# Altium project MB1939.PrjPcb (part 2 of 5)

## Sheet MEMs_microphone.SchDoc: MEMs_microphone
size A4; Date: Not used; ApprovedBy: Not used; CheckedBy: Not used; Author: Not used; CompanyName: STMicroelectronics; DrawnBy: Not used; Engineer: Not used; Organization: Not used; Address1: Not used; Address2: Not used; Address3: Not used; Address4: Not used; DocumentNumber: Not used; Revision: Not used; SheetNumber: 16; SheetTotal: 21
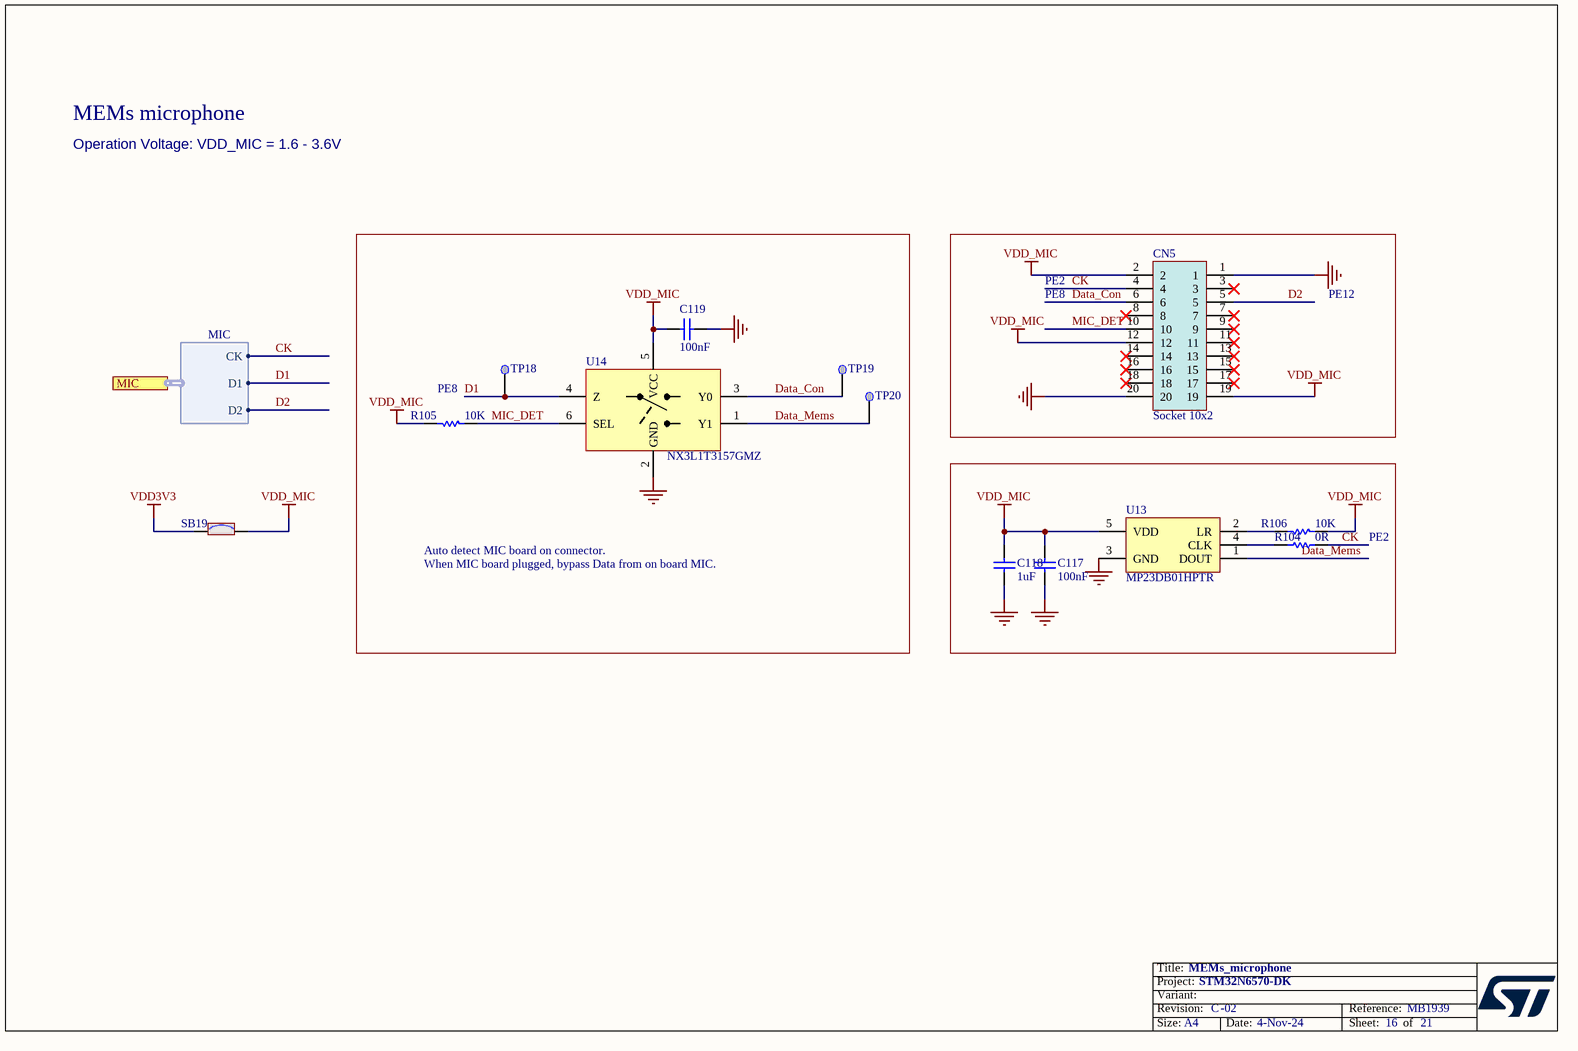
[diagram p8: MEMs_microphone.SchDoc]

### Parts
C117  value 100nF  [C0402]  (hidden comment: Capacitor)
C118  value 1uF  [C0402]  (hidden comment: Capacitor)
C119  value 100nF  [C0402]  (hidden comment: Capacitor)
CN5  Socket 10x2  [CON_FCI_20021311-XXX20XXLF]
R104  value 0R  [R0402]  (hidden comment: Resistor)
R105  value 10K  [R0402]  (hidden comment: Resistor)
R106  value 10K  [R0402]  (hidden comment: Resistor)
SB19  SB_ON  [SOLDER-BRIDGE_R0402-0R]  (value not drawn)
TP18  Test Point  [TP_SMD_1MM]  (value not drawn)  (no BOM)
TP19  Test Point  [TP_SMD_1MM]  (value not drawn)  (no BOM)
TP20  Test Point  [TP_SMD_1MM]  (value not drawn)  (no BOM)
U13  value MP23DB01HPTR  [MIC_STM_MP23DB01MMTR]  (hidden comment: MP23DB01MMTR)
U14  value NX3L1T3157GMZ  [ICC_SOT886_XSON6]  (hidden comment: NX3L1T3157GM)

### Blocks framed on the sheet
PE2: C117 C118 R104 R106 U13

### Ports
MIC (harness MIC)

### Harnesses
MIC: CK, D1, D2

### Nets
GND: C117.1 C118.1 C119.1 CN5.1 CN5.20 U13.3(GND) U14.2(GND)
VDD3V3: SB19.1
VDD_MIC: C117.2 C118.2 C119.2 CN5.2 CN5.12 CN5.19 R105.2 R106.1 SB19.2 U13.5(VDD) U14.5(VCC)
CK: CN5.4 R104.2 ; port MIC.CK
D1: TP18.1 U14.4(Z) ; port MIC.D1
D2: CN5.5 ; port MIC.D2
Data_Con: CN5.6 TP19.1 U14.3(Y0)
Data_Mems: TP20.1 U13.1(DOUT) U14.1(Y1)
MIC_DET: CN5.10 R105.1 U14.6(SEL)
NetR104_1: R104.1 U13.4(CLK)
NetR106_2: R106.2 U13.2(LR)

Not connected (* = marked no-connect by the designer): CN5 3* 7* 8* 9* 11* 13* 14* 15* 16* 17* 18*

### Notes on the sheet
- MEMs microphone
- Operation Voltage: VDD_MIC = 1.6 - 3.6V
- PE2
- PE8
- PE12
- (near R105) PE8
- Auto detect MIC board on connector.
- When MIC board plugged, bypass Data from on board MIC.
- Title:
- Project:
- Size:
- Revision:
- Variant:
- A4
- -
- Date:
- Reference:
- Sheet:
- of

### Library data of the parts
C117 C119 = MCD-00006: Capacitor, MLCC, 100nF, 16V, X7R, +/-10%, 0402, T=0.5mm; Manufacturer_Part_Number: CC0402KRX7R7BB104; Manufacturer: YAGEO; Part_Preference: Recommended; Partial_Alternate_Internal_Part_Number: MCD-03299; Order_Code_RS: 9402047; Component_Country_Of_Origin: China; ShowFields: YES; ID: 2474
C118 = MCD-00095: Capacitor, MLCC, 1uF, 25V, X5R, +/-10%, 0402, T=0.5mm; Part_Preference: Recommended; Manufacturer: MURATA; Manufacturer_Part_Number: GRM155R61E105KA12; Partial_Alternate_Internal_Part_Number: MCD-04188; Order_Code_RS: 2218855; Component_Country_Of_Origin: Japan°°; ShowFields: YES; ID: 2772
CN5 = MCD-00147: Socket, 10x2, 1.27mm, VR, TH, T=4.30mm/2.40mm; Part_Type: Connector; Part_Preference: Recommended; Manufacturer: AMPHENOL CS; Manufacturer_Part_Number: 20021311-00020T4LF; Partial_Alternate_Internal_Part_Number: MCD-03007; Order_Code_RS: 170-8859; Component_Country_Of_Origin: China; ShowFields: YES; ID: 2719
R104 = MCD-00052: Resistor, 0R, 0402, +/-5%, 1/16W; Manufacturer_Part_Number: RC0402JR-070RL; Manufacturer: YAGEO; Part_Preference: Recommended; Order_Code_RS: 9232516RL; Component_Country_Of_Origin: China; ShowFields: YES; ID: 2540
R105 R106 = MCD-00053: Resistor, 10K, 0402, +/-1%, 1/16W; Manufacturer_Part_Number: RC0402FR-0710KL; Manufacturer: YAGEO; BMS_Part_Number: 9131590; Part_Preference: Recommended; Order_Code_RS: 9239359; Component_Country_Of_Origin: China; ShowFields: YES; ID: 2539
SB19 = MCD-01618: Resistor, 0R, SB0402, 5%, 0.063W; Manufacturer_Part_Number: RC0402JR-070RL; Manufacturer: YAGEO; Part_Preference: Recommended; Order_Code_RS: 618-5804; Component_Country_Of_Origin: China; ShowFields: YES; ID: 3718
TP18-TP20 = MCD-00074: Test Point, SMD, 1mm; Part_Type: Misc; Part_Preference: Recommended; ShowFields: YES; ID: 2518; Component_Country_Of_Origin: Unknown
U13 = MCD-02122: MEMS, Audio sensor Multi performance mode digital microphone; Part_Type: IC; Manufacturer: STMICROELECTRONICS; Part_Preference: Recommended; Manufacturer_HQ_COO: EU; Component_Country_Of_Origin: China; ShowFields: YES; ID: 4222
U14 = MCD-02386: Analog Switch, Low-ohmic single-pole double-throw analog switch; Part_Type: IC; Part_Preference: Recommended; Manufacturer: NXP; Partial_Alternate_Internal_Part_Number: MCD-03199; Component_Country_Of_Origin: Thailand; ShowFields: YES; ID: 4492

## Sheet OctoSPI_Flash.SchDoc: OctoSPI_Flash
size A4; Date: Not used; ApprovedBy: Not used; CheckedBy: Not used; Author: Not used; CompanyName: STMicroelectronics; DrawnBy: Not used; Engineer: Not used; Organization: Not used; Address1: Not used; Address2: Not used; Address3: Not used; Address4: Not used; DocumentNumber: Not used; Revision: Not used; SheetNumber: 7; SheetTotal: 21
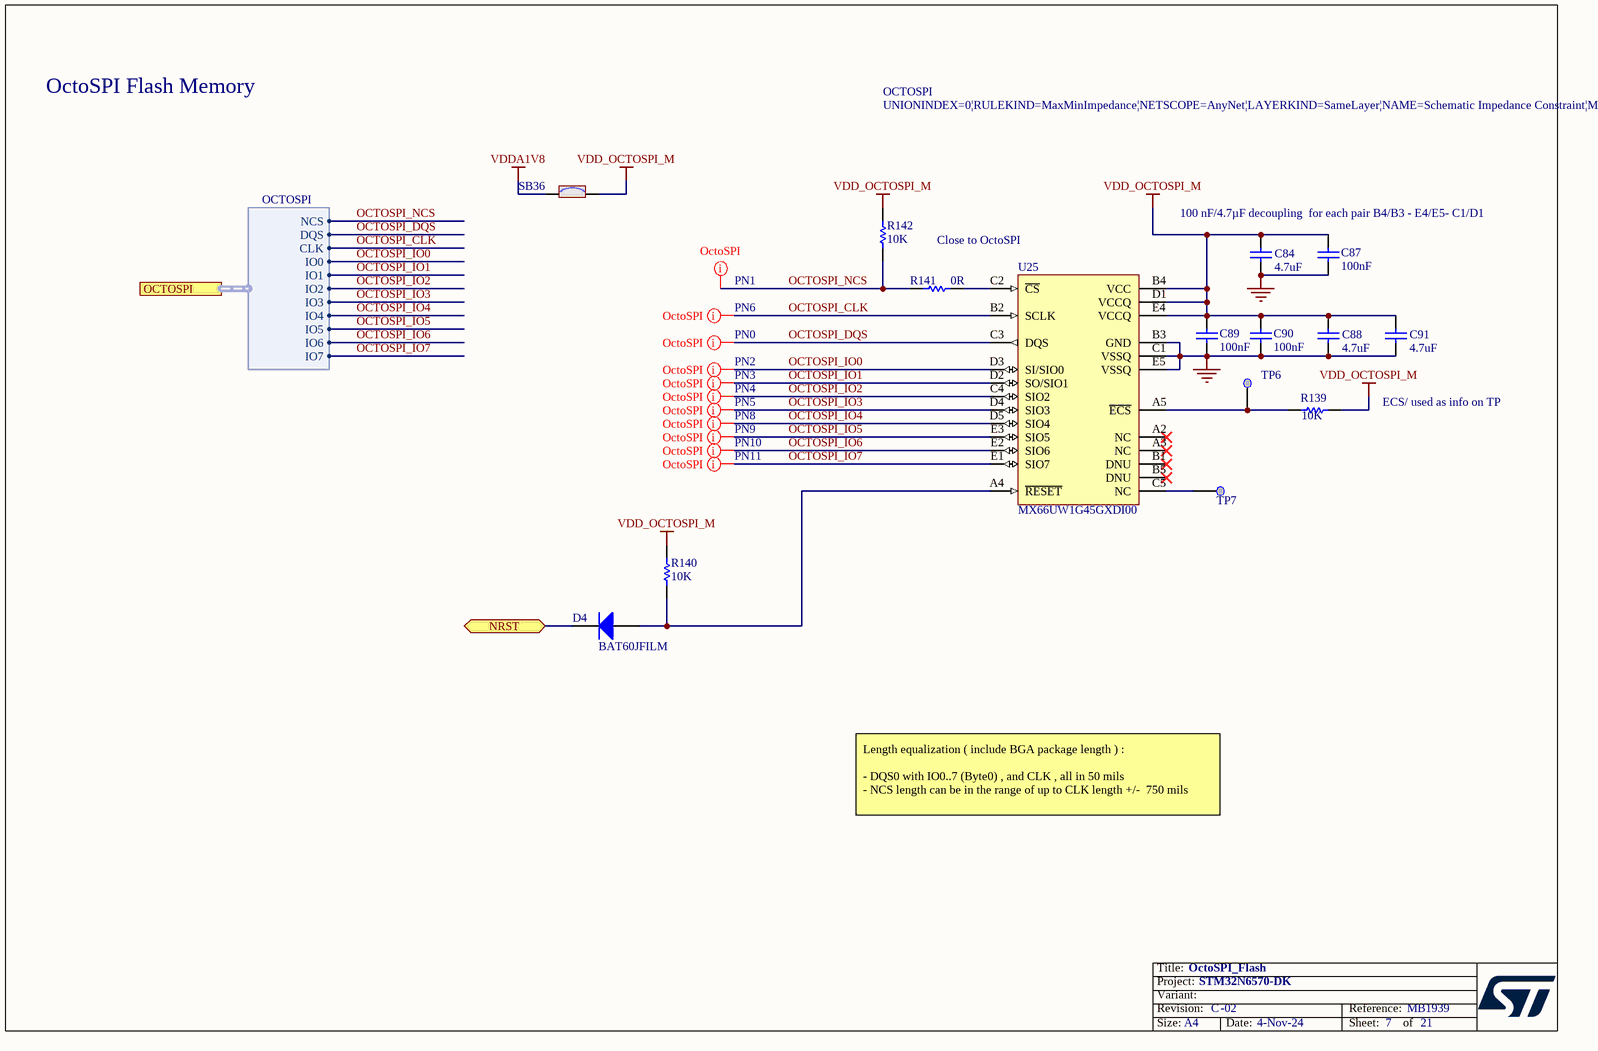
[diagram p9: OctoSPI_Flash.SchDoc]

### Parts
C84  value 4.7uF  [C0603]  (hidden comment: Capacitor)
C87  value 100nF  [C0402]  (hidden comment: Capacitor)
C88  value 4.7uF  [C0603]  (hidden comment: Capacitor)
C89  value 100nF  [C0402]  (hidden comment: Capacitor)
C90  value 100nF  [C0402]  (hidden comment: Capacitor)
C91  value 4.7uF  [C0603]  (hidden comment: Capacitor)
D4  BAT60JFILM  [DIO_SOD323]
R139  value 10K  [R0402]  (hidden comment: Resistor)
R140  value 10K  [R0402]  (hidden comment: Resistor)
R141  value 0R  [R0402]  (hidden comment: Resistor)
R142  value 10K  [R0402]  (hidden comment: Resistor)
SB36  SB_ON  [SOLDER-BRIDGE_R0402-0R]  (value not drawn)
TP6  Test Point  [TP_SMD_1MM]  (value not drawn)  (no BOM)
TP7  Test Point  [TP_SMD_1MM]  (value not drawn)  (no BOM)
U25  MX66UW1G45GXDI00  [ICC_BGA24_5X5-BALL-ARRAY_6X8_P1]

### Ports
NRST (bidir), OCTOSPI (harness OCTOSPI)

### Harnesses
OCTOSPI: IO1, IO0, CLK, NCS, IO2, IO3, IO5, IO4, IO6, IO7, DQS

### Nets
GND: C84.1 C87.1 C88.1 C89.1 C90.1 C91.1 U25.B3(GND) U25.C1(VSSQ) U25.E5(VSSQ)
VDD_OCTOSPI_M: C84.2 C87.2 C88.2 C89.2 C90.2 C91.2 R139.2 R140.2 R142.2 SB36.2 U25.B4(VCC) U25.D1(VCCQ) U25.E4(VCCQ)
VDDA1V8: SB36.1
NRST: D4.2(K) ; port NRST
OCTOSPI_CLK: U25.B2(SCLK) ; port OCTOSPI.CLK
OCTOSPI_DQS: U25.C3(DQS) ; port OCTOSPI.DQS
OCTOSPI_IO0: U25.D3(SI/SIO0) ; port OCTOSPI.IO0
OCTOSPI_IO1: U25.D2(SO/SIO1) ; port OCTOSPI.IO1
OCTOSPI_IO2: U25.C4(SIO2) ; port OCTOSPI.IO2
OCTOSPI_IO3: U25.D4(SIO3) ; port OCTOSPI.IO3
OCTOSPI_IO4: U25.D5(SIO4) ; port OCTOSPI.IO4
OCTOSPI_IO5: U25.E3(SIO5) ; port OCTOSPI.IO5
OCTOSPI_IO6: U25.E2(SIO6) ; port OCTOSPI.IO6
OCTOSPI_IO7: U25.E1(SIO7) ; port OCTOSPI.IO7
OCTOSPI_NCS: R141.1 R142.1 ; port OCTOSPI.NCS
NetD4_1: D4.1(A) R140.1 U25.A4(~{RESET})
NetR139_1: R139.1 TP6.1 U25.A5(~{ECS})
NetR141_2: R141.2 U25.C2(~{CS})
NetTP7_1: TP7.1 U25.C5(NC)

Not connected (* = marked no-connect by the designer): U25 A2(NC)* A3(NC)* B1(DNU)* B5(DNU)*

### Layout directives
rule Matched Net Lengths [Tolerance = 1000mil]; net class OCTOSPI; rule Impedance Constraint [Min = 45.00    Max = 55.00    ]; rule Routing Layers [TopLayer - Enabled BottomLayer - Disabled]: OCTOSPI_NCS
rule Matched Net Lengths [Tolerance = 10mil]; net class OCTOSPI; rule Impedance Constraint [Min = 45.00    Max = 55.00    ]; rule Routing Layers [TopLayer - Enabled BottomLayer - Disabled]: OCTOSPI_CLK
rule Matched Net Lengths [Tolerance = 20mil]; net class OCTOSPI; rule Impedance Constraint [Min = 45.00    Max = 55.00    ]; rule Routing Layers [TopLayer - Enabled BottomLayer - Disabled]: OCTOSPI_DQS, OCTOSPI_IO0, OCTOSPI_IO1, OCTOSPI_IO2, OCTOSPI_IO3, OCTOSPI_IO4, OCTOSPI_IO5, OCTOSPI_IO6, OCTOSPI_IO7

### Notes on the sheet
- OctoSPI Flash Memory
- Close to OctoSPI
- 100 nF/4.7µF decoupling  for each pair B4/B3 - E4/E5- C1/D1
- PN1
- PN6
- PN3
- PN2
- PN0
- PN10
- PN9
- PN5
- PN8
- PN4
- ECS/ used as info on TP
- PN11
- Length equalization ( include BGA package length ) :
  - DQS0 with IO0..7 (Byte0) , and CLK , all in 50 mils
  - NCS length can be in the range of up to CLK length +/-  750 mils
- Title:
- Project:
- Size:
- Revision:
- Variant:
- A4
- -
- Date:
- Reference:
- Sheet:
- of

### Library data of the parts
C84 C88 C91 = MCD-00009: Capacitor, MLCC, 4.7uF, 16V, X5R, +/-10%, 0603, T=0.8mm; Manufacturer_Part_Number: CC0603KRX5R7BB475; Manufacturer: YAGEO; Part_Preference: Recommended; Partial_Alternate_Internal_Part_Number: MCD-03565; Component_Country_Of_Origin: China; ShowFields: YES; ID: 2471; Alternate_EMS: A
C87 C89 C90 = MCD-00006: as C117 on sheet MEMs_microphone
D4 = MCD-00034: Diode, Schottky, 0V53, 1A, 10V, SOD323; Manufacturer: STMICROELECTRONICS; BMS_Part_Number: 9151097; Part_Preference: Recommended; Manufacturer_HQ_COO: EU; Component_Country_Of_Origin: China; ShowFields: YES; ID: 2483; Order_Code_RS: 714-6879
R139 R140 R142 = MCD-00053: as R105 on sheet MEMs_microphone
R141 = MCD-00052: as R104 on sheet MEMs_microphone
SB36 = MCD-01618: as SB19 on sheet MEMs_microphone
TP6 TP7 = MCD-00074: as TP18 on sheet MEMs_microphone
U25 = MCD-02601: Memory, Serial NOR Flash, 1V8, 1Gbit, 200MHz, BGA-24; Part_Type: IC; Part_Preference: Recommended; Manufacturer: MACRONIX; Manufacturer_HQ_COO: Unknown; ShowFields: YES; ID: 4707; Component_Country_Of_Origin: Taiwan

## Sheet SDcard.SchDoc: SD Card
size A4; Date: Not used; ApprovedBy: Not used; CheckedBy: Not used; Author: Not used; CompanyName: STMicroelectronics; DrawnBy: Not used; Engineer: Not used; Organization: Not used; Address1: Not used; Address2: Not used; Address3: Not used; Address4: Not used; DocumentNumber: Not used; Revision: Not used; SheetNumber: 14; SheetTotal: 21
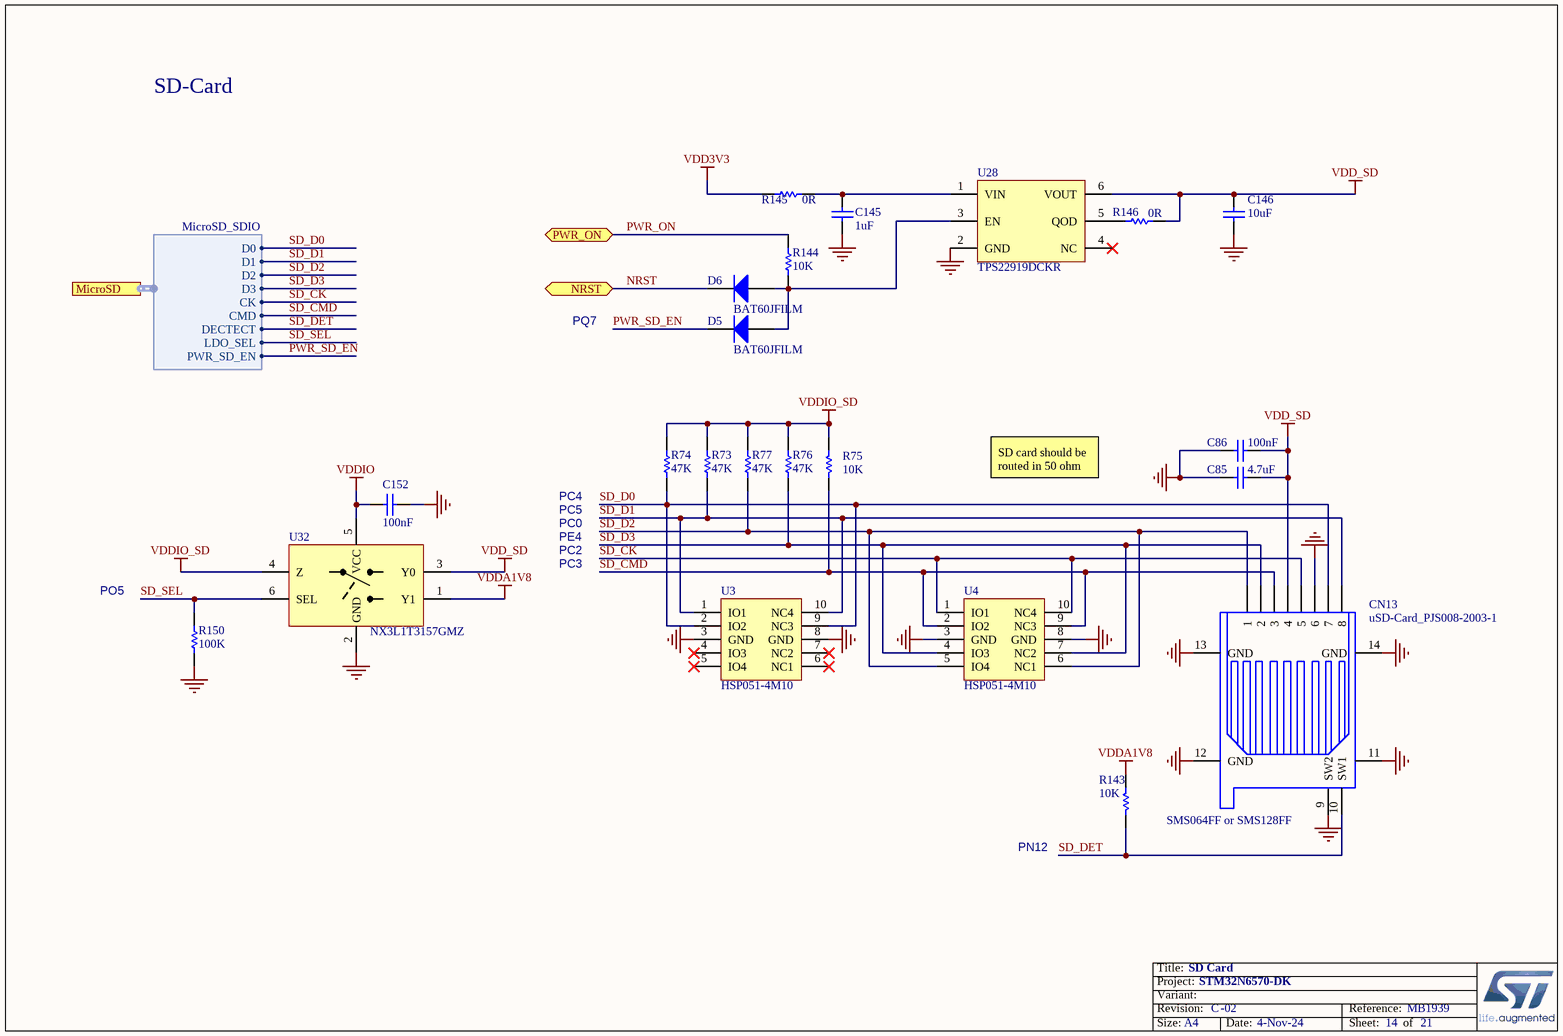
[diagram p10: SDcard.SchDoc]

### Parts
C85  value 4.7uF  [C0603]  (hidden comment: Capacitor)
C86  value 100nF  [C0402]  (hidden comment: Capacitor)
C145  value 1uF  [C0402]  (hidden comment: Capacitor)
C146  value 10uF  [C0603]  (hidden comment: Capacitor)
C152  value 100nF  [C0402]  (hidden comment: Capacitor)
CN13  value uSD-Card_PJS008-2003-1  [CON_MICROSD_YAMAICHI_PJS008-2003-1]  (hidden comment: microSD-PJS008-2003)
D5  BAT60JFILM  [DIO_SOD323]
D6  BAT60JFILM  [DIO_SOD323]
R73  value 47K  [R0402]  (hidden comment: Resistor)
R74  value 47K  [R0402]  (hidden comment: Resistor)
R75  value 10K  [R0402]  (hidden comment: Resistor)
R76  value 47K  [R0402]  (hidden comment: Resistor)
R77  value 47K  [R0402]  (hidden comment: Resistor)
R143  value 10K  [R0402]  (hidden comment: Resistor)
R144  value 10K  [R0402]  (hidden comment: Resistor)
R145  value 0R  [R0603]  (hidden comment: Resistor)
R146  value 0R  [R0402]  (hidden comment: Resistor)
R150  value 100K  [R0402]  (hidden comment: Resistor)
U3  HSP051-4M10  [ESD_UQFN-10L_2P5X1_P050]
U4  HSP051-4M10  [ESD_UQFN-10L_2P5X1_P050]
U28  value TPS22919DCKR  [ICC_SC70-6_DCK_R-PDSO-G6_2X1P25_P065]  (hidden comment: TPS22919)
U32  value NX3L1T3157GMZ  [ICC_SOT886_XSON6]  (hidden comment: NX3L1T3157GM)

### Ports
MicroSD (harness MicroSD_SDIO), NRST (bidir), PWR_ON (bidir)

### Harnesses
MicroSD_SDIO: D0, D1, D2, D3, CK, CMD, DECTECT, LDO_SEL, PWR_SD_EN

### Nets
GND: C85.2 C86.1 C145.1 C146.1 C152.1 CN13.6 CN13.9(SW2) CN13.11(GND) CN13.12(GND) CN13.13(GND) CN13.14(GND) R150.1 U3.3(GND) U3.8(GND) U4.3(GND) U4.8(GND) U28.2(GND) U32.2(GND)
VDD3V3: R145.1
VDD_SD: C85.1 C86.2 C146.2 CN13.4 R146.2 U28.6(VOUT) U32.3(Y0)
VDDA1V8: R143.2 U32.1(Y1)
VDDIO: C152.2 U32.5(VCC)
VDDIO_SD: R73.2 R74.2 R75.2 R76.2 R77.2 U32.4(Z)
NRST: D6.2(K) ; port NRST
PWR_ON: R144.1 ; port PWR_ON
PWR_SD_EN: D5.2(K) ; port MicroSD.PWR_SD_EN  [project net PQ7]
SD_CK: CN13.5 U4.1(IO1) U4.10(NC4) ; port MicroSD.CK  [project net PC2]
SD_CMD: CN13.3 R75.1 U4.2(IO2) U4.9(NC3) ; port MicroSD.CMD  [project net PC3]
SD_D0: CN13.7 R74.1 U3.2(IO2) U3.9(NC3) ; port MicroSD.D0  [project net PC4]
SD_D1: CN13.8 R73.1 U3.1(IO1) U3.10(NC4) ; port MicroSD.D1  [project net PC5]
SD_D2: CN13.1 R77.1 U4.5(IO4) U4.6(NC1) ; port MicroSD.D2  [project net PC0]
SD_D3: CN13.2 R76.1 U4.4(IO3) U4.7(NC2) ; port MicroSD.D3  [project net PE4]
SD_DET: CN13.10(SW1) R143.1 ; port MicroSD.DECTECT  [project net PN12]
SD_SEL: R150.2 U32.6(SEL) ; port MicroSD.LDO_SEL  [project net PO5]
NetC145_2: C145.2 R145.2 U28.1(VIN)
NetD5_1: D5.1(A) D6.1(A) R144.2 U28.3(EN)
NetR146_1: R146.1 U28.5(QOD)

Not connected (* = marked no-connect by the designer): U3 4(IO3)* 5(IO4)* 6(NC1)* 7(NC2)*; U28 4(NC)*

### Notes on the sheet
- SD-Card
- PQ7
- PC4
- PC5
- SD card should be routed in 50 ohm
- PC0
- PE4
- PC3
- PC2
- PO5
- PN12
- SMS064FF or SMS128FF

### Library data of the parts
C85 = MCD-00009: as C84 on sheet OctoSPI_Flash
C86 C152 = MCD-00006: as C117 on sheet MEMs_microphone
C145 = MCD-00095: Capacitor, MLCC, 1uF, 25V, X5R, +/-10%, 0402, T=0.5mm; Manufacturer_Part_Number: GRM155R61E105KA12; Manufacturer: MURATA; Part_Preference: Recommended; Partial_Alternate_Internal_Part_Number: MCD-04188; Order_Code_RS: 2218855; Component_Country_Of_Origin: Japan°°; ShowFields: YES; ID: 2772
C146 = MCD-00099: Capacitor, MLCC, 10uF, 10V, X5R, +/-10%, 0603, T=0.8mm; Manufacturer_Part_Number: GRM188R61A106KE69D; Manufacturer: MURATA; Part_Preference: Recommended; Partial_Alternate_Internal_Part_Number: MCD-03152; Order_Code_RS: 2494233; Component_Country_Of_Origin: Japan°°; ShowFields: YES; ID: 2770
CN13 = MCD-00023: Connector_uSD Card, Reversed-Type, Mnt Push-Push; Manufacturer_Part_Number: PJS008-2003-1; Manufacturer: YAMAICHI; Part_Preference: Recommended; Component_Country_Of_Origin: Unknown; ShowFields: YES; ID: 2492
D5 D6 = MCD-00034: as D4 on sheet OctoSPI_Flash
R73 R74 R76 R77 = MCD-00063: Resistor, 47K, 0402, +/-1%, 1/16W; Manufacturer_Part_Number: RC0402FR-0747KL; Manufacturer: YAGEO; Part_Preference: Recommended; Order_Code_RS: 9239430; Component_Country_Of_Origin: China; ShowFields: YES; ID: 2528
R75 R143 R144 = MCD-00053: as R105 on sheet MEMs_microphone
R145 = MCD-00056: Resistor, 0R, 0603, +/-5%, 1/10W; Manufacturer_Part_Number: RC0603JR-070RL; Manufacturer: YAGEO; Part_Preference: Recommended; Order_Code_RS: 9233130RL; Component_Country_Of_Origin: China; ShowFields: YES; ID: 2536
R146 = MCD-00052: as R104 on sheet MEMs_microphone
R150 = MCD-00059: Resistor, 100K, 0402, +/-1%, 1/16W; Manufacturer_Part_Number: RC0402FR-07100KL; Manufacturer: YAGEO; Part_Preference: Recommended; Partial_Alternate_Internal_Part_Number: MCD-03301; Order_Code_RS: 2421891; Component_Country_Of_Origin: China; ID: 2533; ShowFields: YES
U3 U4 = MCD-00667: Diode, ESD protection, 3V6, 100nA, 5V8, uQFN-10; Manufacturer: STMICROELECTRONICS; BMS_Part_Number: 9179041; Part_Preference: Recommended; Manufacturer_HQ_COO: EU; Component_Country_Of_Origin: Philippines; ShowFields: YES; ID: 3081
U28 = MCD-02311: IC, 5V5, 1.5A, 90mR Self-Protected load switch with controlled rise time; Part_Preference: Recommended; Manufacturer: TEXAS INSTRUMENTS; Component_Country_Of_Origin: Thailand; ShowFields: YES; ID: 4417
U32 = MCD-02386: as U14 on sheet MEMs_microphone

## Sheet STLINK_V3EC.SchDoc: STLINK-V3EC
size A3; Date: Not used; ApprovedBy: Not used; CheckedBy: Not used; Author: Not used; CompanyName: STMicroelectronics; DrawnBy: Not used; Engineer: Not used; Organization: Not used; Address1: Not used; Address2: Not used; Address3: Not used; Address4: Not used; DocumentNumber: Not used; Revision: V0.2; SheetNumber: 19; SheetTotal: 21
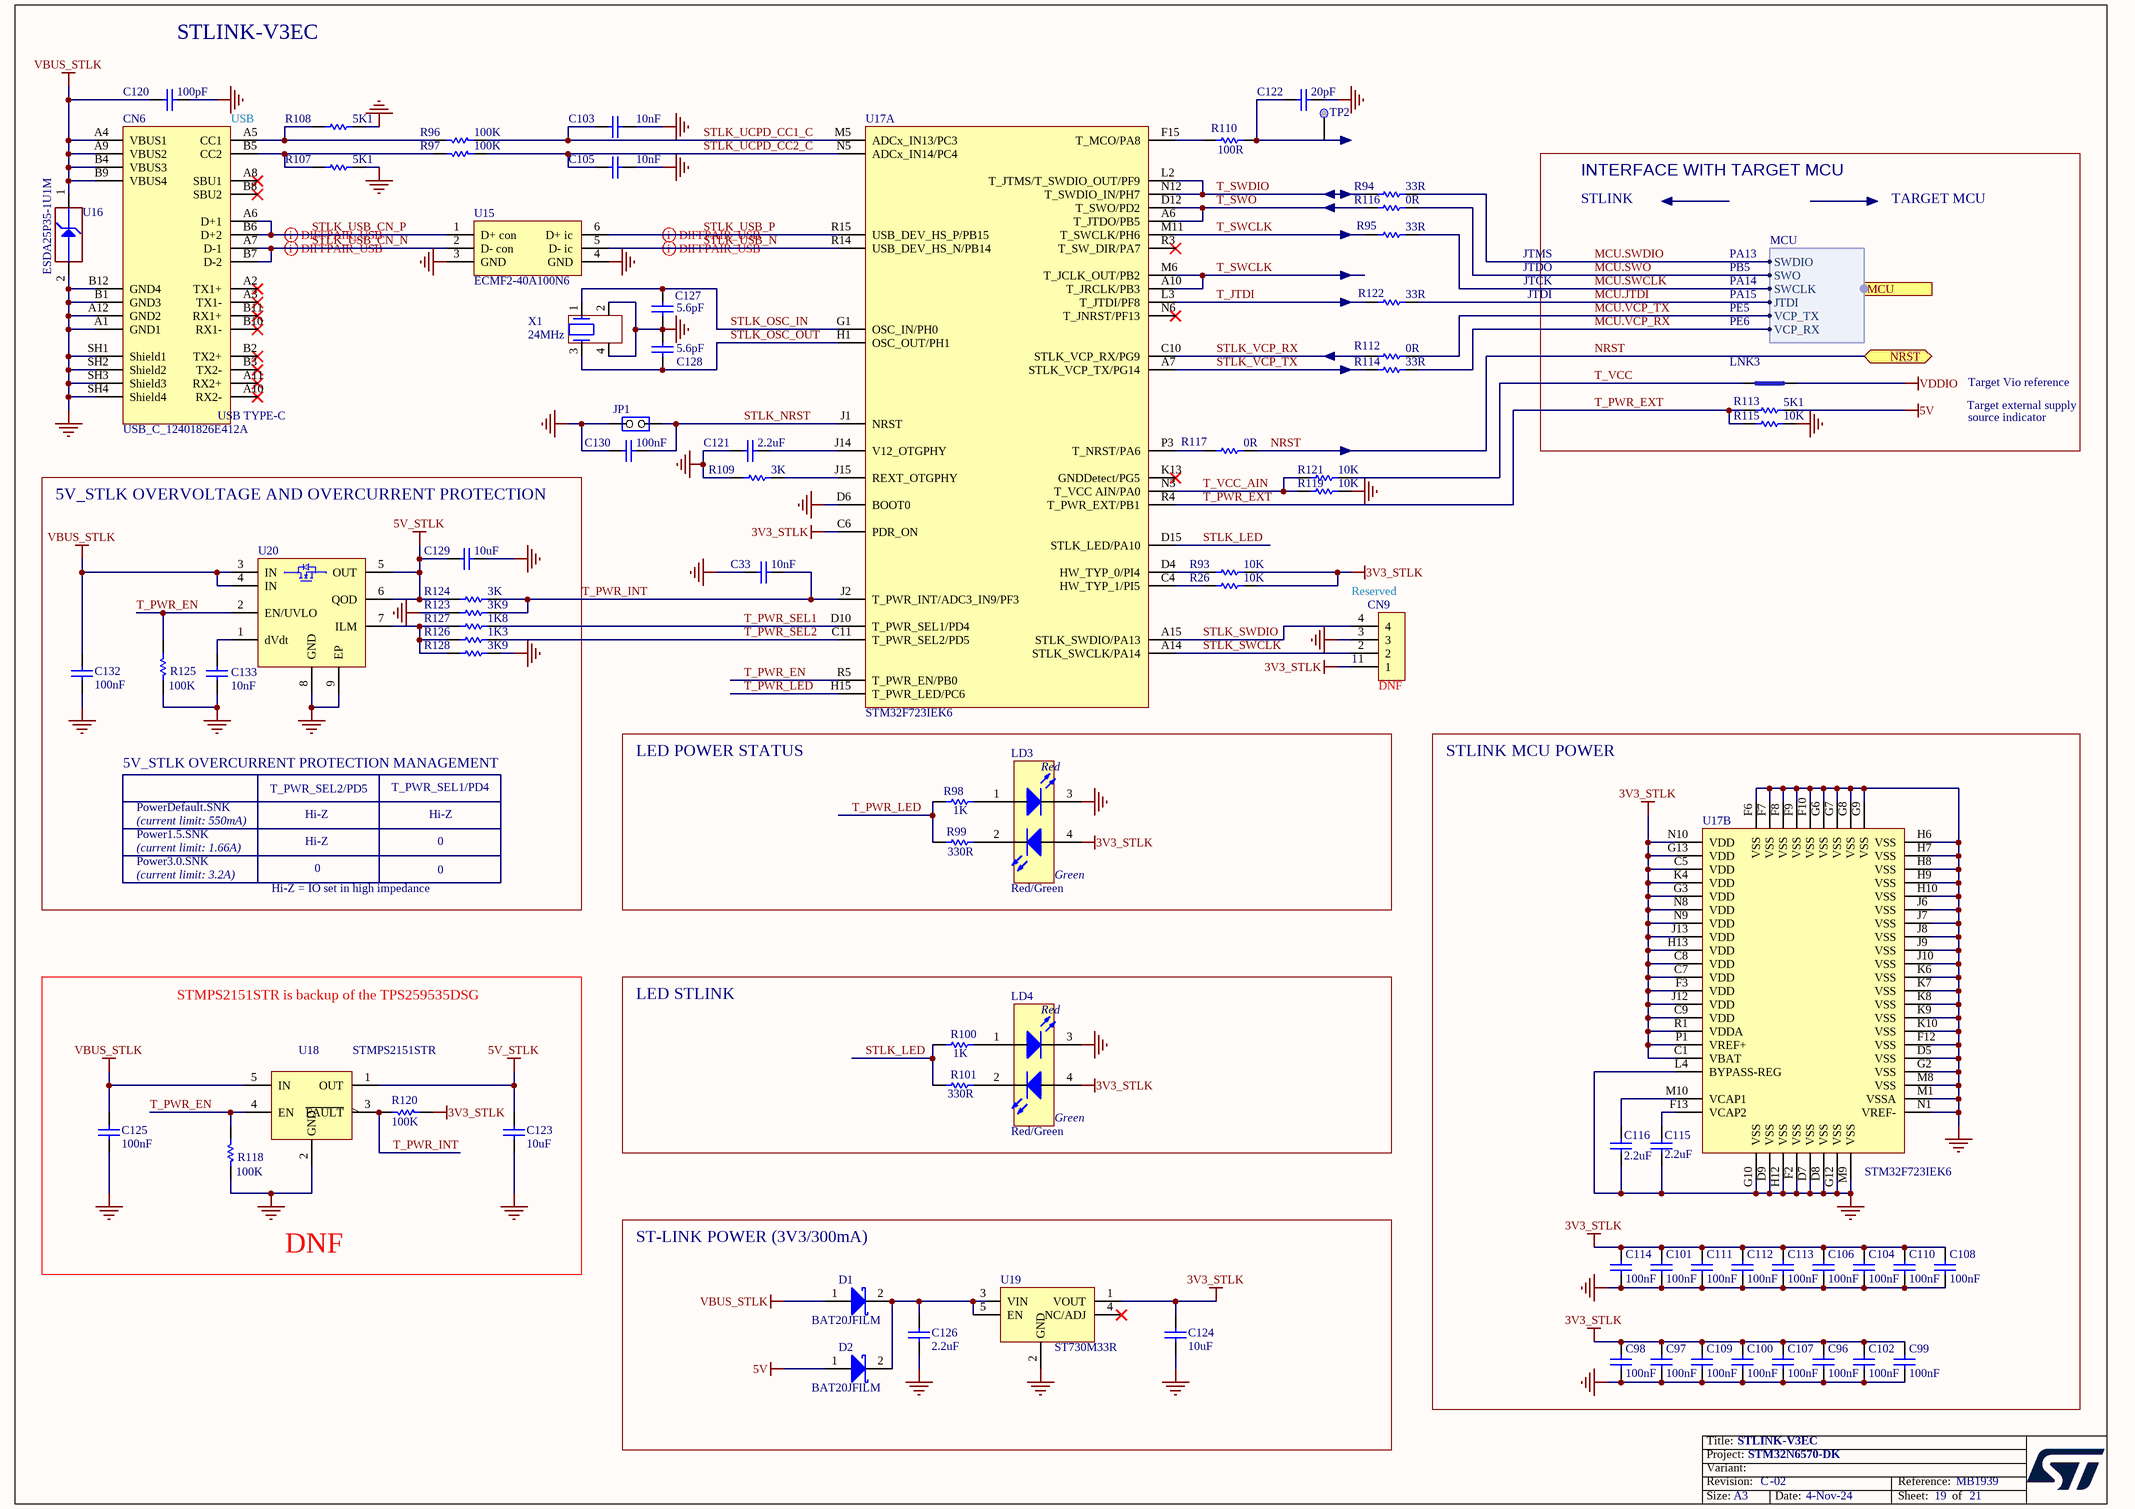
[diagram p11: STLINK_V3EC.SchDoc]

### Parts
C33  value 10nF  [C0402]  (hidden comment: Capacitor)
C96  value 100nF  [C0402]  (hidden comment: Capacitor)
C97  value 100nF  [C0402]  (hidden comment: Capacitor)
C98  value 100nF  [C0402]  (hidden comment: Capacitor)
C99  value 100nF  [C0402]  (hidden comment: Capacitor)
C100  value 100nF  [C0402]  (hidden comment: Capacitor)
C101  value 100nF  [C0402]  (hidden comment: Capacitor)
C102  value 100nF  [C0402]  (hidden comment: Capacitor)
C103  value 10nF  [C0402]  (hidden comment: Capacitor)
C104  value 100nF  [C0402]  (hidden comment: Capacitor)
C105  value 10nF  [C0402]  (hidden comment: Capacitor)
C106  value 100nF  [C0402]  (hidden comment: Capacitor)
C107  value 100nF  [C0402]  (hidden comment: Capacitor)
C108  value 100nF  [C0402]  (hidden comment: Capacitor)
C109  value 100nF  [C0402]  (hidden comment: Capacitor)
C110  value 100nF  [C0402]  (hidden comment: Capacitor)
C111  value 100nF  [C0402]  (hidden comment: Capacitor)
C112  value 100nF  [C0402]  (hidden comment: Capacitor)
C113  value 100nF  [C0402]  (hidden comment: Capacitor)
C114  value 100nF  [C0402]  (hidden comment: Capacitor)
C115  value 2.2uF  [C0402]  (hidden comment: Capacitor)
C116  value 2.2uF  [C0402]  (hidden comment: Capacitor)
C120  value 100pF  [C0402]  (hidden comment: Capacitor)
C121  value 2.2uF  [C0402]  (hidden comment: Capacitor)
C122  value 20pF  [C0402]  (hidden comment: Capacitor)
C123  value 10uF  [C0603]  (hidden comment: Capacitor)
C124  value 10uF  [C0603]  (hidden comment: Capacitor)
C125  value 100nF  [C0402]  (hidden comment: Capacitor)
C126  value 2.2uF  [C0805]  (hidden comment: Capacitor)
C127  value 5.6pF  [C0402]  (hidden comment: Capacitor)
C128  value 5.6pF  [C0402]  (hidden comment: Capacitor)
C129  value 10uF  [C0603]  (hidden comment: Capacitor)
C130  value 100nF  [C0402]  (hidden comment: Capacitor)
C132  value 100nF  [C0402]  (hidden comment: Capacitor)
C133  value 10nF  [C0402]  (hidden comment: Capacitor)
CN6  value USB_C_12401826E412A  [CON_USB-TYPEC_AMPHENOL_12401826E412A]  (hidden comment: USB_TYPE_C_Receptacle)
CN9  Header 4x1  [CON_SAMTEC_TSW-104-07-G-S]  (value not drawn)
D1  value BAT20JFILM  [DIO_SOD323_1A_2K]  (hidden comment: SCHOTTKY_1A_2K)
D2  value BAT20JFILM  [DIO_SOD323_1A_2K]  (hidden comment: SCHOTTKY_1A_2K)
JP1  Jumper_Header 2x1  [CON_SAMTEC_TSW-102-07-G-S]  (value not drawn)
LD3  value Red/Green  [LED_BI-GR_WE-150141SV73110]  (hidden comment: LED_BICOLOR)
LD4  value Red/Green  [LED_BI-GR_WE-150141SV73110]  (hidden comment: LED_BICOLOR)
LNK3  link_200  [LINK200]  (value not drawn)  (no BOM)
R26  value 10K  [R0402]  (hidden comment: Resistor)
R93  value 10K  [R0402]  (hidden comment: Resistor)
R94  value 33R  [R0402]  (hidden comment: Resistor)
R95  value 33R  [R0402]  (hidden comment: Resistor)
R96  value 100K  [R0402]  (hidden comment: Resistor)
R97  value 100K  [R0402]  (hidden comment: Resistor)
R98  value 1K  [R0402]  (hidden comment: Resistor)
R99  value 330R  [R0402]  (hidden comment: Resistor)
R100  value 1K  [R0402]  (hidden comment: Resistor)
R101  value 330R  [R0402]  (hidden comment: Resistor)
R107  value 5K1  [R0402]  (hidden comment: Resistor)
R108  value 5K1  [R0402]  (hidden comment: Resistor)
R109  value 3K  [R0402]  (hidden comment: Resistor)
R110  value 100R  [R0402]  (hidden comment: Resistor)
R112  value 0R  [R0402]  (hidden comment: Resistor)
R113  value 5K1  [R0402]  (hidden comment: Resistor)
R114  value 33R  [R0402]  (hidden comment: Resistor)
R115  value 10K  [R0402]  (hidden comment: Resistor)
R116  value 0R  [R0402]  (hidden comment: Resistor)
R117  value 0R  [R0402]  (hidden comment: Resistor)
R118  value 100K  [R0402]  (hidden comment: Resistor)
R119  value 10K  [R0402]  (hidden comment: Resistor)
R120  value 100K  [R0402]  (hidden comment: Resistor)
R121  value 10K  [R0402]  (hidden comment: Resistor)
R122  value 33R  [R0402]  (hidden comment: Resistor)
R123  value 3K9  [R0402]  (hidden comment: Resistor)
R124  value 3K  [R0402]  (hidden comment: Resistor)
R125  value 100K  [R0402]  (hidden comment: Resistor)
R126  value 1K3  [R0402]  (hidden comment: Resistor)
R127  value 1K8  [R0402]  (hidden comment: Resistor)
R128  value 3K9  [R0402]  (hidden comment: Resistor)
TP2  Test Point  [TP_SMD_1MM]  (value not drawn)  (no BOM)
U15  ECMF2-40A100N6  [ESD_UQFN-6L_1P45X1P4_P040]
U16  value ESDA25P35-1U1M  [ESD_QFN1610_2N_1K_2A]  (hidden comment: ESD-TRANSIL)
U17  value STM32F723IEK6  [ICC_UFBGA201_176+25_10X10_P065]  (hidden comment: STLINK-V3EC)  (parts A,B of 3)
U18  STMPS2151STR  [MOS_SOT23-5L]
U19  ST730M33R  [ICC_SOT23-5L_H1P45]
U20  TPS259535DSG  [ICC_WSON8-EPAD_2X2_P050]  (value not drawn)
X1  value 24MHz  [CRY_NX2016SA_4P]  (hidden comment: XTAL_4_PINS)

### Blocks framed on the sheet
INTERFACE WITH TARGET MCU: LNK3 R113 R115
5V_STLK OVERVOLTAGE AND OVERCURRENT PROTECTION: C129 C132 C133 R123-R128 U20
LED POWER STATUS: LD3 R98 R99
STLINK MCU POWER: C96-C102 C104 C106-C116 U17
DNF: C123 C125 R118 R120 U18
LED STLINK: LD4 R100 R101
ST-LINK POWER (3V3/300mA): C124 C126 D1 D2 U19

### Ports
MCU (harness MCU), NRST (bidir)

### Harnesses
MCU: SWDIO, SWO, VCP_TX, SWCLK, VCP_RX, JTDI

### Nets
3V3_STLK: C96.1 C97.1 C98.1 C99.1 C100.1 C101.1 C102.1 C104.1 C106.1 C107.1 C108.1 C109.1 C110.1 C111.1 C112.1 C113.1 C114.1 C124.2 CN9.1 LD3.4(Green_anode) LD4.4(Green_anode) R26.2 R93.2 R120.1 U17.C1(VBAT) U17.C5(VDD) U17.C6(PDR_ON) U17.C7(VDD) U17.C8(VDD) U17.C9(VDD) U17.F3(VDD) U17.G3(VDD) U17.G13(VDD) U17.H13(VDD) U17.J12(VDD) U17.J13(VDD) U17.K4(VDD) U17.N8(VDD) U17.N9(VDD) U17.N10(VDD) U17.P1(VREF+) U17.R1(VDDA) U19.1(VOUT)
5V: D2.1(A) R113.2
5V_STLK: C123.2 C129.2 R124.1 U18.1(OUT) U20.5(OUT) U20.6(QOD)
GND: C33.2 C96.2 C97.2 C98.2 C99.2 C100.2 C101.2 C102.2 C103.2 C104.2 C105.2 C106.2 C107.2 C108.2 C109.2 C110.2 C111.2 C112.2 C113.2 C114.2 C115.1 C116.1 C120.2 C121.1 C122.1 C123.1 C124.1 C125.1 C126.1 C127.2 C128.1 C129.1 C130.1 C132.1 C133.1 CN6.A1(GND1) CN6.A12(GND2) CN6.B1(GND3) CN6.B12(GND4) CN6.SH1(Shield1) CN6.SH2(Shield2) CN6.SH3(Shield3) CN6.SH4(Shield4) CN9.3 JP1.2(NO) LD3.3(RED_cathode) LD4.3(RED_cathode) R107.2 R108.2 R109.2 R115.2 R118.1 R119.2 R123.2 R125.1 R128.2 U15.3(GND) U15.4(GND) U16.2(GND) U17.D5(VSS) U17.D6(BOOT0) U17.D7(VSS) U17.D8(VSS) U17.D9(VSS) U17.F2(VSS) U17.F6(VSS) U17.F7(VSS) U17.F8(VSS) U17.F9(VSS) U17.F10(VSS) U17.F12(VSS) U17.G2(VSS) U17.G6(VSS) U17.G7(VSS) U17.G8(VSS) U17.G9(VSS) U17.G10(VSS) U17.G12(VSS) U17.H6(VSS) U17.H7(VSS) U17.H8(VSS) U17.H9(VSS) U17.H10(VSS) U17.H12(VSS) U17.J6(VSS) U17.J7(VSS) U17.J8(VSS) U17.J9(VSS) U17.J10(VSS) U17.K6(VSS) U17.K7(VSS) U17.K8(VSS) U17.K9(VSS) U17.K10(VSS) U17.L4(BYPASS-REG) U17.M1(VSSA) U17.M8(VSS) U17.M9(VSS) U17.N1(VREF-) U18.2(GND) U19.2(GND) U20.8(GND) U20.9(EP) X1.2 X1.4
VBUS_STLK: C120.1 C125.2 C132.2 CN6.A4(VBUS1) CN6.A9(VBUS2) CN6.B4(VBUS3) CN6.B9(VBUS4) D1.1(A) U16.1(IO1) U18.5(IN) U20.3(IN) U20.4(IN)
VDDIO: LNK3.1
MCU.JTDI: R122.2 ; port MCU.JTDI
MCU.SWCLK: R95.2 ; port MCU.SWCLK
MCU.SWDIO: R94.2 ; port MCU.SWDIO
MCU.SWO: R116.2 ; port MCU.SWO
MCU.VCP_RX: R114.2 ; port MCU.VCP_RX
MCU.VCP_TX: R112.2 ; port MCU.VCP_TX
NRST: R117.2 ; port NRST
STLK_LED: R100.2 R101.1 U17.D15(STLK_LED/PA10)
STLK_NRST: C130.2 JP1.1(COMMON) U17.J1(NRST)
STLK_OSC_IN: C127.1 U17.G1(OSC_IN/PH0) X1.1
STLK_OSC_OUT: C128.2 U17.H1(OSC_OUT/PH1) X1.3
STLK_SWCLK: CN9.2 U17.A14(STLK_SWCLK/PA14)
STLK_SWDIO: CN9.4 U17.A15(STLK_SWDIO/PA13)
STLK_UCPD_CC1_C: C103.1 R96.1 U17.M5(ADCx_IN13/PC3)
STLK_UCPD_CC2_C: C105.1 R97.1 U17.N5(ADCx_IN14/PC4)
STLK_USB_CN_N: CN6.A7(D-1) CN6.B7(D-2) U15.2(D-_con)
STLK_USB_CN_P: CN6.A6(D+1) CN6.B6(D+2) U15.1(D+_con)
STLK_USB_N: U15.5(D-_ic) U17.R14(USB_DEV_HS_N/PB14)
STLK_USB_P: U15.6(D+_ic) U17.R15(USB_DEV_HS_P/PB15)
STLK_VCP_RX: R112.1 U17.C10(STLK_VCP_RX/PG9)
STLK_VCP_TX: R114.1 U17.A7(STLK_VCP_TX/PG14)
T_JTDI: R122.1 U17.L3(T_JTDI/PF8)
T_PWR_EN: R118.2 R125.2 U17.R5(T_PWR_EN/PB0) U18.4(EN) U20.2(EN/UVLO)
T_PWR_EXT: R113.1 R115.1 U17.R4(T_PWR_EXT/PB1)
T_PWR_INT: C33.1 R120.2 R123.1 R124.2 U17.J2(T_PWR_INT/ADC3_IN9/PF3) U18.3(~{FAULT})
T_PWR_LED: R98.2 R99.2 U17.H15(T_PWR_LED/PC6)
T_PWR_SEL1: R127.2 U17.D10(T_PWR_SEL1/PD4)
T_PWR_SEL2: R126.2 U17.C11(T_PWR_SEL2/PD5)
T_SWCLK: R95.1 U17.A10(T_JRCLK/PB3) U17.M6(T_JCLK_OUT/PB2) U17.M11(T_SWCLK/PH6)
T_SWDIO: R94.1 U17.L2(T_JTMS/T_SWDIO_OUT/PF9) U17.N12(T_SWDIO_IN/PH7)
T_SWO: R116.1 U17.A6(T_JTDO/PB5) U17.D12(T_SWO/PD2)
T_VCC: LNK3.2 R121.2
T_VCC_AIN: R119.1 R121.1 U17.N3(T_VCC_AIN/PA0)
NetC115_2: C115.2 U17.F13(VCAP2)
NetC116_2: C116.2 U17.M10(VCAP1)
NetC121_2: C121.2 U17.J14(V12_OTGPHY)
NetC122_2: C122.2 R110.2 TP2.1
NetC126_2: C126.2 D1.2(K) D2.2(K) U19.3(VIN) U19.5(EN)
NetC133_2: C133.2 U20.1(dVdt)
NetCN6_A5: CN6.A5(CC1) R96.2 R108.1
NetCN6_B5: CN6.B5(CC2) R97.2 R107.1
NetLD3_1: LD3.1(Red_anode) R98.1
NetLD3_2: LD3.2(Green_cathode) R99.1
NetLD4_1: LD4.1(Red_anode) R100.1
NetLD4_2: LD4.2(Green_cathode) R101.2
NetR26_1: R26.1 U17.C4(HW_TYP_1/PI5)
NetR93_1: R93.1 U17.D4(HW_TYP_0/PI4)
NetR109_1: R109.1 U17.J15(REXT_OTGPHY)
NetR110_1: R110.1 U17.F15(T_MCO/PA8)
NetR117_1: R117.1 U17.P3(T_NRST/PA6)
NetR126_1: R126.1 R127.1 R128.1 U20.7(ILM)

Not connected (* = marked no-connect by the designer): CN6 A2(TX1+)* A3(TX1-)* A8(SBU1)* A10(RX2-)* A11(RX2+)* B2(TX2+)* B3(TX2-)* B8(SBU2)* B10(RX1-)* B11(RX1+)*; U17 K13(GNDDetect/PG5)* N6(T_JNRST/PF13)* R3(T_SW_DIR/PA7)*; U19 4(NC/ADJ)*

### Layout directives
differential pair; rule Impedance Constraint [Min = 85.00    Max = 95.00    ]: STLK_USB_CN_N, STLK_USB_CN_P, STLK_USB_N, STLK_USB_P

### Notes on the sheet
- STLINK-V3EC
- (near CN6) USB
- STLINK
- TARGET MCU
- JTMS
- JTDO
- JTCK
- JTDI
- PA13
- PA14
- PB5
- PA15
- PE5
- PE6
- Target external supply
- Target Vio reference
- source indicator
- (near CN9) Reserved
- (near CN9) 1
- (near CN9) DNF
- 5V_STLK OVERCURRENT PROTECTION MANAGEMENT
- (current limit: 550mA)
- (current limit: 1.66A)
- Power1.5.SNK
- PowerDefault.SNK
- T_PWR_SEL2/PD5
- Hi-Z
- T_PWR_SEL1/PD4
- 0
- (current limit: 3.2A)
- Power3.0.SNK
- Hi-Z = IO set in high impedance
- STMPS2151STR is backup of the TPS259535DSG

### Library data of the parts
C33 = MCD-00011: Capacitor, MLCC, 10nF, 16V, X7R, +/-10%, 0402, T=0.5mm; Part_Preference: Recommended; Manufacturer: YAGEO; Manufacturer_Part_Number: CC0402KRX7R7BB103; Order_Code_RS: 3019275; Component_Country_Of_Origin: China; ShowFields: YES; ID: 2469
C96-C102 C104 C106-C114 C130 = MCD-00006: as C117 on sheet MEMs_microphone
C103 C105 C133 = MCD-02198: Capacitor, MLCC, 10nF, 50V, X7R, +/-10%, 0402, T=0.5mm; Part_Preference: Recommended; Manufacturer: YAGEO; Manufacturer_Part_Number: CC0402KRX7R9BB103; Order_Code_RS: 6169644; Component_Country_Of_Origin: China; ShowFields: YES; ID: 4298
C115 C116 C121 = MCD-02606: Capacitor, MLCC, 2.2uF, 6.3V, X5R, +/-10%, 0402, T=0.5mm; Part_Preference: Recommended; Manufacturer: YAGEO; Manufacturer_Part_Number: CC0402KRX5R5BB225; Order_Code_RS: 1992205; ShowFields: YES; ID: 4712; Component_Country_Of_Origin: China°
C120 = MCD-00205: Capacitor, MLCC, 100pF, 50V, NPO, +/-5%, 0402, T=0.5mm; Part_Preference: Recommended; Manufacturer: YAGEO; Manufacturer_Part_Number: CC0402JRNPO9BN101; Component_Country_Of_Origin: China; ShowFields: YES; ID: 2658
C122 = MCD-00016: Capacitor, MLCC, 20pF, 50V, NPO, +/- 5%, 0402, T=0.5mm; Manufacturer_Part_Number: CC0402JRNPO9BN200; Manufacturer: YAGEO; Part_Preference: Recommended; Component_Country_Of_Origin: China; ShowFields: YES; ID: 2479
C123 C124 C129 = MCD-00099: Capacitor, MLCC, 10uF, 10V, X5R, +/-10%, 0603, T=0.8mm; Part_Preference: Recommended; Manufacturer: MURATA; Manufacturer_Part_Number: GRM188R61A106KE69D; Partial_Alternate_Internal_Part_Number: MCD-03152; Order_Code_RS: 2494233; Component_Country_Of_Origin: Japan°°; ShowFields: YES; ID: 2770
C125 C132 = MCD-02355: Capacitor, MLCC, 100nF, 25V, X7R, +/-10%, 0402, T=0.5mm; Part_Preference: Recommended; Manufacturer: WALSIN TECHNOLOGY CORPORATION; Manufacturer_Part_Number: 0402B104K250CT; Partial_Alternate_Internal_Part_Number: MCD-03302, MCD-03304; Order_Code_RS: 176-3114; Component_Country_Of_Origin: Unknown; ShowFields: YES; ID: 4461
C126 = MCD-02372: Capacitor, MLCC, 2.2uF, 25V, X7R, +/-10%, 0805, T=1,25mm; Manufacturer_Part_Number: GRM21BR71E225KE11L; Manufacturer: MURATA; Part_Preference: Recommended; Partial_Alternate_Internal_Part_Number: MCD-04185; Component_Country_Of_Origin: Japan°; ShowFields: YES; ID: 4478
C127 C128 = MCD-01374: Capacitor, MLCC, 5.6pF, 50V, NPO, +/-0.1pF, 0402, T=0.5mm; Part_Preference: Recommended; Manufacturer: YAGEO; Manufacturer_Part_Number: CC0402BRNPO9BN5R6; Component_Country_Of_Origin: China; ShowFields: YES; ID: 3474
CN6 = MCD-03232: USB_TypeC, 24 pins, RA, SMD, T=2.96mm; Part_Type: Connector; Part_Preference: Recommended; Manufacturer: AMPHENOL CS; Manufacturer_Part_Number: 12401826E412A; Component_Country_Of_Origin: China°; ShowFields: YES; ID: 5348
CN9 = MCD-00029: Header, 4x1, 2.54mm, VR, TH, T=5.84mm/2.54mm; Manufacturer_Part_Number: TSW-104-07-G-S; Manufacturer: SAMTEC; Part_Type: Connector; Part_Preference: Recommended; Order_Code_RS: 161-2460; Component_Country_Of_Origin: China, Costa Rica, Malaysia, USA, Vietnam; ShowFields: YES; ID: 2487
D1 D2 = MCD-03011: Diode, Schottky, 0V54, 1A, 23V, SOD-323; Part_Preference: Recommended; Manufacturer: STMICROELECTRONICS; Order_Code_RS: 165-7545; ShowFields: YES; ID: 5127; Component_Country_Of_Origin: China
JP1 = MCD-00045: Header, 2x1, 2.54mm, VR, TH, T=5.84mm/2.54mm; Part_Preference: Recommended; Part_Type: Connector; Manufacturer: SAMTEC; Manufacturer_Part_Number: TSW-102-07-G-S; Full_Alternate_Internal_Part_Number: MCD-02390; Partial_Alternate_Internal_Part_Number: MCD-02957, MCD-03720, MCD-04249; Order_Code_RS: 2505044; Component_Country_Of_Origin: China, Costa Rica, Malaysia, USA, Vietnam; ShowFields: YES; ID: 2545
LD3 LD4 = MCD-02631: LED Bicolor, Red/Green, 2V, 20mA, 4-PLCC; Part_Type: Display; Part_Preference: Recommended; Manufacturer: WURTH ELEKTRONIK; Manufacturer_Part_Number: 150141SV73110; Partial_Alternate_Internal_Part_Number: MCD-02402; Order_Code_RS: 184-6963; Component_Country_Of_Origin: China; ShowFields: YES; ID: 4737
LNK3 = MCD-02777: Track link on PCB 200um width for layout routing; Part_Type: Misc; Part_Preference: Recommended; ShowFields: YES; ID: 4889; Component_Country_Of_Origin: Unknown
R26 R93 R115 R119 R121 = MCD-00053: as R105 on sheet MEMs_microphone
R94 R95 R114 R122 = MCD-00455: Resistor, 33R, 0402, +/-1%, 1/16W; Part_Preference: Recommended; Manufacturer: YAGEO; Manufacturer_Part_Number: RC0402FR-0733RL; Component_Country_Of_Origin: China; ShowFields: YES; ID: 2821
R96 R97 R118 R120 R125 = MCD-00059: Resistor, 100K, 0402, +/-1%, 1/16W; Manufacturer_Part_Number: RC0402FR-07100KL; Manufacturer: YAGEO; Part_Preference: Recommended; Partial_Alternate_Internal_Part_Number: MCD-03301; Order_Code_RS: 2421891; Component_Country_Of_Origin: China; ShowFields: YES; ID: 2533
R98 R100 = MCD-02665: Resistor, 1K, 0402, +/-0.1%, 1/16W, +/-25ppm/°C; Part_Preference: Recommended; Manufacturer: YAGEO; Manufacturer_Part_Number: RT0402BRD071KL; Order_Code_RS: 199-1298; ShowFields: YES; ID: 4771; Component_Country_Of_Origin: Taiwan
R99 R101 = MCD-00062: Resistor, 330R, 0402, +/-1%, 1/16W; Part_Preference: Recommended; Manufacturer: YAGEO; Manufacturer_Part_Number: RC0402FR-07330RL; Order_Code_RS: 9239170; Component_Country_Of_Origin: China; ShowFields: YES; ID: 2529
R107 R108 R113 = MCD-00333: Resistor, 5K1, 0402, +/-1%, 1/16W; Part_Preference: Recommended; Manufacturer: YAGEO; Manufacturer_Part_Number: RC0402FR-075K1L; Component_Country_Of_Origin: China; ShowFields: YES; ID: 2944
R109 = MCD-00185: Resistor, 3K, 0402, +/-1%, 1/16W; Manufacturer_Part_Number: RC0402FR-073KL; Manufacturer: YAGEO; Part_Preference: Recommended; Component_Country_Of_Origin: China; ShowFields: YES; ID: 2682
R110 = MCD-00067: Resistor, 100R, 0402, +/- 1%, 1/16W; Part_Preference: Recommended; Manufacturer: YAGEO; Manufacturer_Part_Number: RC0402FR-07100RL; Order_Code_RS: 9239111; Component_Country_Of_Origin: China; ShowFields: YES; ID: 2527
R112 R116 R117 = MCD-00052: Resistor, 0R, 0402, +/-5%, 1/16W; Part_Preference: Recommended; Manufacturer: YAGEO; Manufacturer_Part_Number: RC0402JR-070RL; Order_Code_RS: 9232516RL; Component_Country_Of_Origin: China; ShowFields: YES; ID: 2540
R123 R128 = MCD-02455: Resistor, 3K9, 0402, +/-1%, 1/16W, +/-100ppm/°C; Part_Preference: Recommended; Manufacturer: YAGEO; Manufacturer_Part_Number: RC0402FR-073K9L; Order_Code_RS: 198-7783; Component_Country_Of_Origin: China; ShowFields: YES; ID: 4561
R124 = MCD-00185: Resistor, 3K, 0402, +/-1%, 1/16W; Part_Preference: Recommended; Manufacturer: YAGEO; Manufacturer_Part_Number: RC0402FR-073KL; Component_Country_Of_Origin: China; ShowFields: YES; ID: 2682
R126 = MCD-00381: Resistor, 1K3, 0402, +/-1%, 1/16W; Part_Preference: Recommended; Manufacturer: YAGEO; Manufacturer_Part_Number: RC0402FR-071K3L; Component_Country_Of_Origin: China; ShowFields: YES; ID: 2898
R127 = MCD-00409: Resistor, 1K8, 0402, +/-1%, 1/16W; Part_Preference: Recommended; Manufacturer: YAGEO; Manufacturer_Part_Number: RC0402FR-071K8L; Component_Country_Of_Origin: China; ShowFields: YES; ID: 2871
TP2 = MCD-00074: as TP18 on sheet MEMs_microphone
U15 = MCD-03060: IC, ESD protection and Common Filter High Speed serial Interfaces, 10.7 GHz; Part_Preference: Recommended; Manufacturer: STMICROELECTRONICS; Component_Country_Of_Origin: China; ShowFields: YES; ID: 5176
U16 = MCD-01207: Diode, ESD TVS, 22V, 200nA, 25V8, QFN1610; Manufacturer: STMICROELECTRONICS; BMS_Part_Number: 9179045; Part_Preference: Recommended; Manufacturer_HQ_COO: EU; Component_Country_Of_Origin: China; ShowFields: YES; ID: 3289; Order_Code_RS: 163-9774
U17 = MCD-03851: MCU, ARM Cortex-M7 32-bit, 512KB Flash, 276KB RAM, With Crypto; Part_Type: IC; Part_Preference: Recommended; Manufacturer: STMICROELECTRONICS; BMS_Part_Number: 9175300; Manufacturer_HQ_COO: EU; Order_Code_RS: 135-8241; ShowFields: YES; ID: 5967; Component_Country_Of_Origin: Philippines
U18 = MCD-00159: IC, Enhanced single channel power switches; Manufacturer: STMICROELECTRONICS; BMS_Part_Number: 9159009; Part_Preference: Recommended; Order_Code_RS: 165-5516; Component_Country_Of_Origin: Malaysia; ShowFields: YES; ID: 2708
U19 = MCD-02514: LDO, 300mA, 28V, Low-dropout voltage, with 5uA quiescent current; Part_Type: IC; Part_Preference: Recommended; Manufacturer: STMICROELECTRONICS; Component_Country_Of_Origin: Malaysia; ShowFields: YES; ID: 4620
U20 = MCD-02532: IC, 2V7 to 18V, 4A, 34mR, eFuse with fast overvoltage protection; Part_Preference: Recommended; Manufacturer: TEXAS INSTRUMENTS; ShowFields: YES; ID: 4638; Component_Country_Of_Origin: Thailand
X1 = MCD-01036: Crystal, 24MHz, 6pF, +/-20ppm, 80R, 2.0x1.6mm; BMS_Part_Number: 9157045; Part_Type: Crystal_Osc; Part_Preference: Recommended; Manufacturer: NDK; Manufacturer_Part_Number: NX2016SA-24MHZ-EXS00A-CS10820; Component_Country_Of_Origin: Unknown; ShowFields: YES; ID: 2989

## Sheet STMOD+.SchDoc: Schematic sheet title to update
size A4; Date: Not used; ApprovedBy: Not used; CheckedBy: Not used; Author: Not used; CompanyName: STMicroelectronics; DrawnBy: Not used; Engineer: Not used; Organization: Not used; Address1: Not used; Address2: Not used; Address3: Not used; Address4: Not used; DocumentNumber: Not used; Revision: 0.2; SheetNumber: 10; SheetTotal: 21
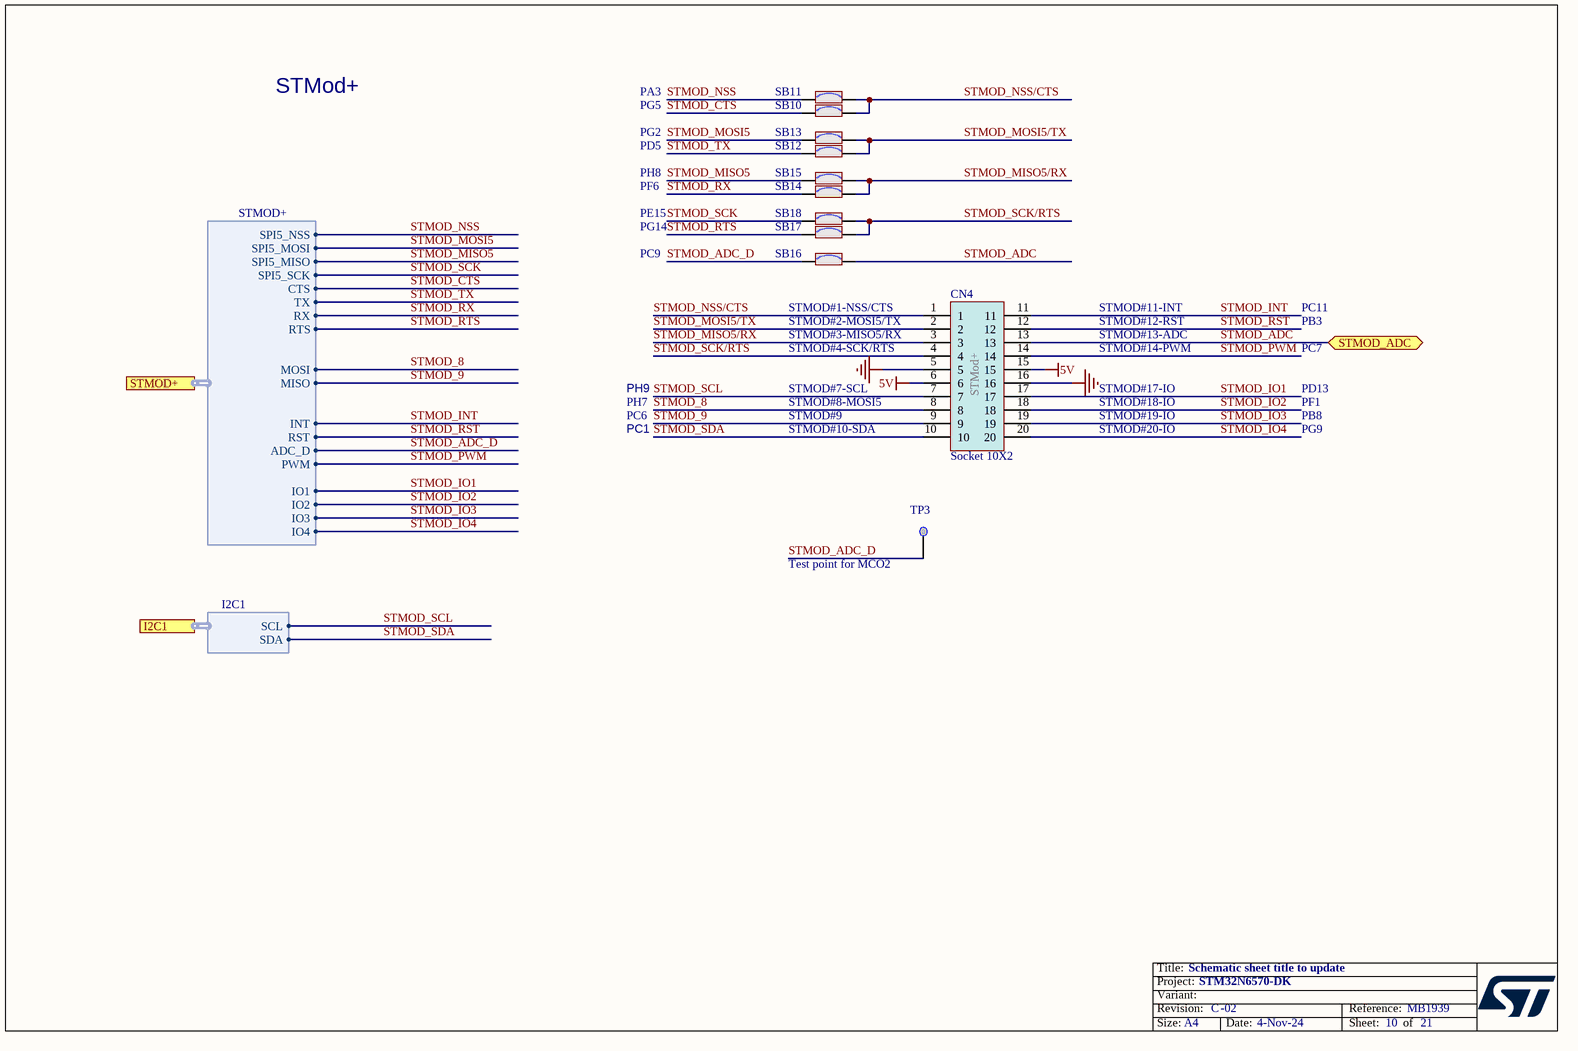
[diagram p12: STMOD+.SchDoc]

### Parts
CN4  value Socket 10X2  [CON_SAMTEC_SQT-110-01-F-D-RA__STMOD+]  (hidden comment: Socket 10X2 STMod+)
SB10  SB_ON  [SOLDER-BRIDGE_R0603-0R]  (value not drawn)
SB11  SB_ON  [SOLDER-BRIDGE_R0603-0R]  (value not drawn)
SB12  SB_ON  [SOLDER-BRIDGE_R0603-0R]  (value not drawn)
SB13  SB_ON  [SOLDER-BRIDGE_R0603-0R]  (value not drawn)
SB14  SB_ON  [SOLDER-BRIDGE_R0603-0R]  (value not drawn)
SB15  SB_ON  [SOLDER-BRIDGE_R0603-0R]  (value not drawn)
SB16  SB_ON  [SOLDER-BRIDGE_R0603-0R]  (value not drawn)
SB17  SB_ON  [SOLDER-BRIDGE_R0603-0R]  (value not drawn)
SB18  SB_ON  [SOLDER-BRIDGE_R0603-0R]  (value not drawn)
TP3  Test Point  [TP_SMD_2MM]  (value not drawn)  (no BOM)

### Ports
I2C1 (harness I2C1), STMOD+ (harness STMOD+), STMOD_ADC (bidir)

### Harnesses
STMOD+: CTS, TX, RX, RTS, MOSI, MISO, INT, RST, ADC_D, PWM, IO1, IO2, IO3, IO4, SPI5_SCK, SPI5_MISO, SPI5_MOSI, SPI5_NSS
I2C1: SCL, SDA

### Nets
5V: CN4.6 CN4.15
GND: CN4.5 CN4.16
STMOD_8: CN4.8 ; port STMOD+.MOSI  [project net PH7]
STMOD_9: CN4.9 ; port STMOD+.MISO  [project net PC6]
STMOD_ADC: CN4.13 SB16.1 ; port STMOD_ADC
STMOD_ADC_D: SB16.2 TP3.1 ; port STMOD+.ADC_D  [project net PC9]
STMOD_CTS: SB10.1 ; port STMOD+.CTS  [project net PG5]
STMOD_INT: CN4.11 ; port STMOD+.INT  [project net PC11]
STMOD_IO1: CN4.17 ; port STMOD+.IO1  [project net PD13]
STMOD_IO2: CN4.18 ; port STMOD+.IO2  [project net PF1]
STMOD_IO3: CN4.19 ; port STMOD+.IO3  [project net PB8]
STMOD_IO4: CN4.20 ; port STMOD+.IO4  [project net PG9]
STMOD_MISO5: SB15.1 ; port STMOD+.SPI5_MISO  [project net ARD_D12]
STMOD_MISO5/RX: CN4.3 SB14.2 SB15.2
STMOD_MOSI5: SB13.1 ; port STMOD+.SPI5_MOSI  [project net ARD_D11]
STMOD_MOSI5/TX: CN4.2 SB12.2 SB13.2
STMOD_NSS: SB11.1 ; port STMOD+.SPI5_NSS  [project net ARD_D10]
STMOD_NSS/CTS: CN4.1 SB10.2 SB11.2
STMOD_PWM: CN4.14 ; port STMOD+.PWM  [project net PC7]
STMOD_RST: CN4.12 ; port STMOD+.RST  [project net PB3]
STMOD_RTS: SB17.1 ; port STMOD+.RTS  [project net PG14]
STMOD_RX: SB14.1 ; port STMOD+.RX  [project net ARD_D0]
STMOD_SCK: SB18.1 ; port STMOD+.SPI5_SCK  [project net ARD_D13]
STMOD_SCK/RTS: CN4.4 SB17.2 SB18.2
STMOD_SCL: CN4.7 ; port I2C1.SCL  [project net ARD_D15]
STMOD_SDA: CN4.10 ; port I2C1.SDA  [project net ARD_D14]
STMOD_TX: SB12.1 ; port STMOD+.TX  [project net ARD_D1]

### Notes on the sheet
- STMod+
- PG5
- PA3
- PD5
- PH8
- PG2
- PF6
- PE15
- PG14
- PC9
- (near SB16) STMOD#1-NSS/CTS
- STMOD#11-INT
- PC11
- STMOD#2-MOSI5/TX
- STMOD#3-MISO5/RX
- STMOD#4-SCK/RTS
- STMOD#12-RST
- STMOD#13-ADC
- STMOD#14-PWM
- PC7
- PB3
- PH7
- PC6
- PH9
- PC1
- STMOD#7-SCL
- STMOD#8-MOSI5
- STMOD#9
- STMOD#10-SDA
- STMOD#17-IO
- STMOD#18-IO
- STMOD#19-IO
- STMOD#20-IO
- PD13
- PB8
- PG9
- PF1
- (near TP3) Test point for MCO2
- Title:
- Project:
- Size:
- Revision:
- Variant:
- A4
- -
- Date:
- Reference:
- Sheet:
- of

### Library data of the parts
CN4 = MCD-00309: Socket, 10x2, 2mm, RA, TH, T=6.35mm/2.29mm; Part_Type: Connector; Manufacturer_Part_Number: SQT-110-01-F-D-RA; Manufacturer: SAMTEC; Part_Preference: Recommended; Partial_Alternate_Internal_Part_Number: MCD-03873; Order_Code_RS: 180-1541; Component_Country_Of_Origin: China, Costa Rica, Malaysia, USA, Vietnam; ShowFields: YES; ID: 2557
SB10-SB18 = MCD-00071: Resistor, 0R, SB0603, 5%, 0.1W; Manufacturer_Part_Number: RC0603JR-070RL; Manufacturer: YAGEO; Part_Preference: Recommended; Manufacturer_HQ_COO: Unknown; ShowFields: YES; ID: 2521; Order_Code_RS: 199-5647; Component_Country_Of_Origin: China
TP3 = MCD-00177: Test Point, SMD, 2mm; Part_Type: Misc; Part_Preference: Recommended; ShowFields: YES; ID: 2690; Component_Country_Of_Origin: Unknown

## Sheet USB2.SchDoc: USB_Host_Hub&TypeC_DRP
size A4; DocumentNumber: MB1341; Revision: A-01; SheetNumber: 18; SheetTotal: 21; Project: STM32MP15-BATTERY BOARD
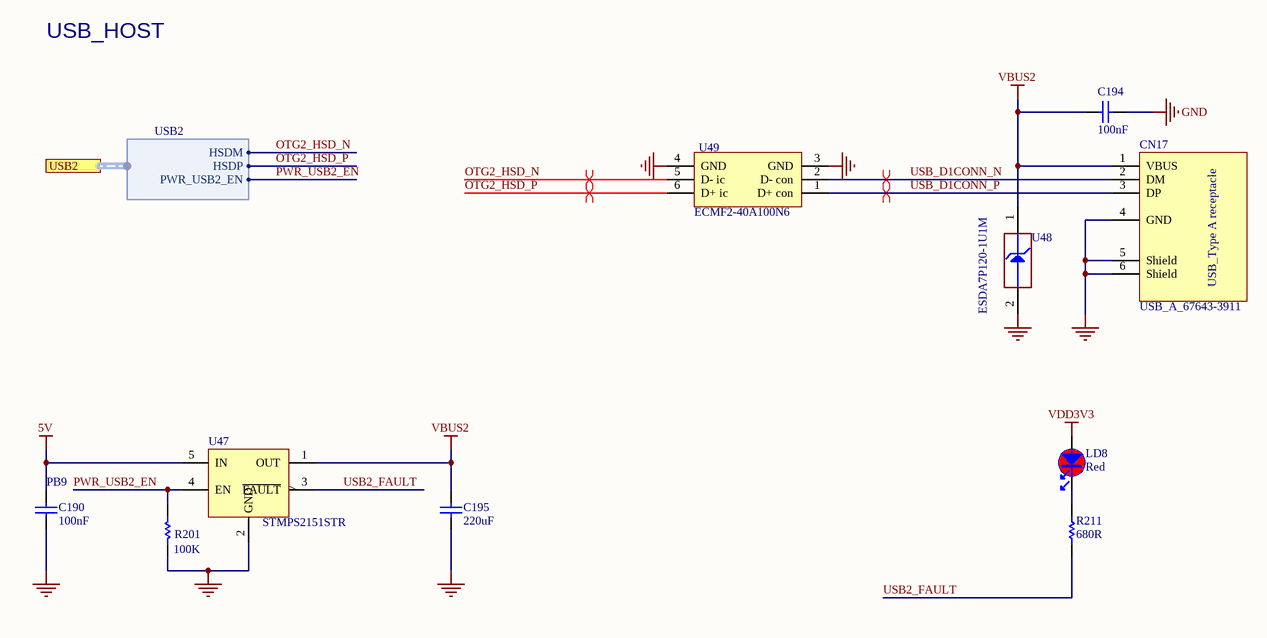
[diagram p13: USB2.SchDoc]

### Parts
C190  value 100nF  [C0402]  (hidden comment: Capacitor)
C194  value 100nF  [C0402]  (hidden comment: Capacitor)
C195  value 220uF  [C1206_H1P6]  (hidden comment: Capacitor)
CN17  value USB_A_67643-3911  [CON_USB-TYPEA_MOLEX_67643-3911_H7P73]  (hidden comment: USB_TypeA_Receptacle_67643-3911)
LD8  value Red  [LED_0603_VISHAY_VLMS1300-GS08_RED_1A2K_H0P8]  (hidden comment: LED_red)
R201  value 100K  [R0402]  (hidden comment: Resistor)
R211  value 680R  [R0402]  (hidden comment: Resistor)
U47  STMPS2151STR  [MOS_SOT23-5L]
U48  value ESDA7P120-1U1M  [ESD_QFN1610_2N_1K_2A]  (hidden comment: ​Footprint needed DFN105P160X60-2N)
U49  ECMF2-40A100N6  [ESD_UQFN-6L_1P45X1P4_P040]

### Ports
USB2 (harness USB2)

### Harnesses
USB2: HSDM, PWR_USB2_EN, HSDP

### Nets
5V: C190.2 U47.5(IN)
GND: C190.1 C194.2 C195.1 CN17.4(GND) CN17.5(Shield) CN17.6(Shield) R201.1 U47.2(GND) U48.2(GND) U49.3(GND) U49.4(GND)
VBUS2: C194.1 C195.2 CN17.1(VBUS) U47.1(OUT) U48.1(IO1)
VDD3V3: LD8.1
OTG2_HSD_N: U49.5(D-_ic) ; port USB2.HSDM
OTG2_HSD_P: U49.6(D+_ic) ; port USB2.HSDP
PWR_USB2_EN: R201.2 U47.4(EN) ; port USB2.PWR_USB2_EN  [project net PB9]
USB2_FAULT: R211.1 U47.3(~{FAULT})
USB_D1CONN_N: CN17.2(DM) U49.2(D-_con)
USB_D1CONN_P: CN17.3(DP) U49.1(D+_con)
NetLD8_2: LD8.2 R211.2

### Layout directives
differential pair: OTG2_HSD_N, OTG2_HSD_P, USB_D1CONN_N, USB_D1CONN_P

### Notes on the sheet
- USB_HOST
- (near C190) PB9

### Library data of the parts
C190 = MCD-02355: as C125 on sheet STLINK_V3EC
C194 = MCD-00006: Capacitor, MLCC, 100nF, 16V, X7R, +/-10%, 0402, T=0.5mm; Part_Preference: Recommended; Manufacturer: YAGEO; Manufacturer_Part_Number: CC0402KRX7R7BB104; Partial_Alternate_Internal_Part_Number: MCD-03299; Order_Code_RS: 9402047; Component_Country_Of_Origin: China; ShowFields: YES; ID: 2474
C195 = MCD-00104: Capacitor, MLCC, 220uF, 6V3, X5R, +/-20%, 1206, T=1.6mm; Part_Preference: Recommended; Manufacturer: MURATA; Manufacturer_Part_Number: GRM31CR60J227ME11; Order_Code_RS: 170-6396; Component_Country_Of_Origin: Japan°°; ShowFields: YES; ID: 2764
CN17 = MCD-01475: USB_TypeA, RA, TH, T= 7.73mm (USB certified); Part_Type: Connector; Manufacturer: MOLEX; Part_Preference: Recommended; Order_Code_RS: 800-6879; Component_Country_Of_Origin: Unknown; ShowFields: YES; ID: 3575
LD8 = MCD-00587: LED, Red, 2V, 20mA, 0603; Manufacturer_Part_Number: VLMS1300-GS08; Manufacturer: VISHAY; Part_Type: Display; Part_Preference: Recommended; Full_Alternate_Internal_Part_Number: MCD-02401; Component_Country_Of_Origin: China; ShowFields: YES; ID: 3154
R201 = MCD-00059: as R96 on sheet STLINK_V3EC
R211 = MCD-00507: Resistor, 680R, 0402, +/-1%, 1/16W; Manufacturer_Part_Number: RC0402FR-07680RL; Manufacturer: YAGEO; Part_Preference: Recommended; Component_Country_Of_Origin: China; ShowFields: YES; ID: 3238
U47 = MCD-00159: as U18 on sheet STLINK_V3EC
U48 = MCD-01026: Diode, ESD TVS, 5V5, 1.5uA, 6V8, QFN1610; Manufacturer: STMICROELECTRONICS; BMS_Part_Number: 9179046; Part_Preference: Recommended; Manufacturer_HQ_COO: EU; Component_Country_Of_Origin: China; ShowFields: YES; ID: 2997; Order_Code_RS: 190-7605
U49 = MCD-03060: as U15 on sheet STLINK_V3EC

## Sheet Mechanical.SchDoc: Mechanical
size A4; Date: Not used; ApprovedBy: Not used; CheckedBy: Not used; Author: Not used; CompanyName: STMicroelectronics; DrawnBy: Not used; Engineer: Not used; Organization: Not used; Address1: Not used; Address2: Not used; Address3: Not used; Address4: Not used; DocumentNumber: Not used; Revision: Not used; SheetNumber: 21; SheetTotal: 21
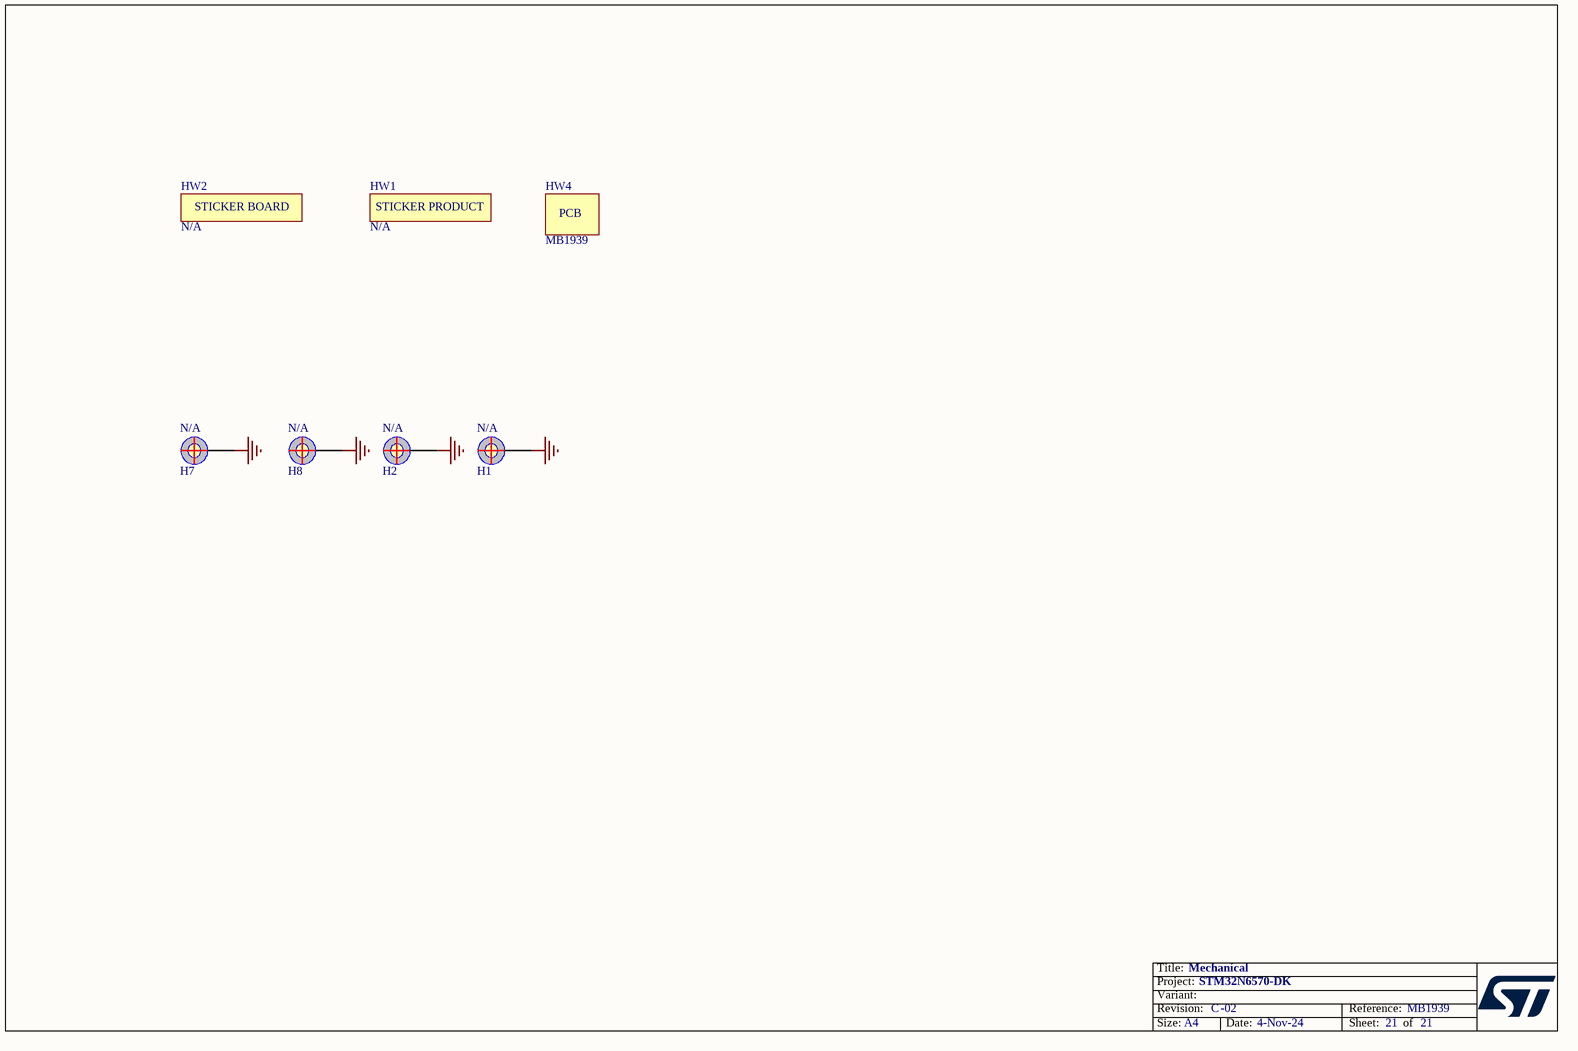
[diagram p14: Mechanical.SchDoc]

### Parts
H1  POSITION HOLE  [PTH_350_700]  (value not drawn)  (no BOM)
H2  POSITION HOLE  [PTH_350_700]  (value not drawn)  (no BOM)
H7  POSITION HOLE  [PTH_350_700]  (value not drawn)  (no BOM)
H8  POSITION HOLE  [PTH_350_700]  (value not drawn)  (no BOM)
HW1  STICKER_PRODUCT  [STICKER_PRODUCT_25X9]  (value not drawn)  (no BOM)
HW2  STICKER_BOARD  [STICKER_BOARD_25X9]  (value not drawn)  (no BOM)
HW4  value MB1939  (hidden comment: PCB)  (no BOM)

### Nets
GND: H1.1 H2.1 H7.1 H8.1

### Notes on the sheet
- Title:
- Project:
- Size:
- Revision:
- Variant:
- A4
- -
- Date:
- Reference:
- Sheet:
- of

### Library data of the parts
H1 H2 H7 H8 = MCD-00328: POSITION HOLE, C7D3R5; Part_Type: Misc; Part_Preference: Recommended; ShowFields: YES; ID: 2950; Component_Country_Of_Origin: Unknown
HW1 = MCD-00547: Sticker product, 25x9mm; Part_Type: Misc; Part_Preference: Recommended; ShowFields: YES; ID: 3197; Component_Country_Of_Origin: Unknown
HW2 = MCD-00235: Sticker Board, 25x9mm; Part_Type: Misc; Part_Preference: Recommended; ShowFields: YES; ID: 2632; Component_Country_Of_Origin: Unknown
HW4 = MCD-04137: PCB MB1939, 6L2S of Main board for STM32N657X0; Part_Preference: Recommended; Manufacturer: XUNJIEXING; Manufacturer_Part_Number: MB1940-N657X0Q-C01_PCB; Component_Country_Of_Origin: China; ShowFields: YES; ID: 6253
